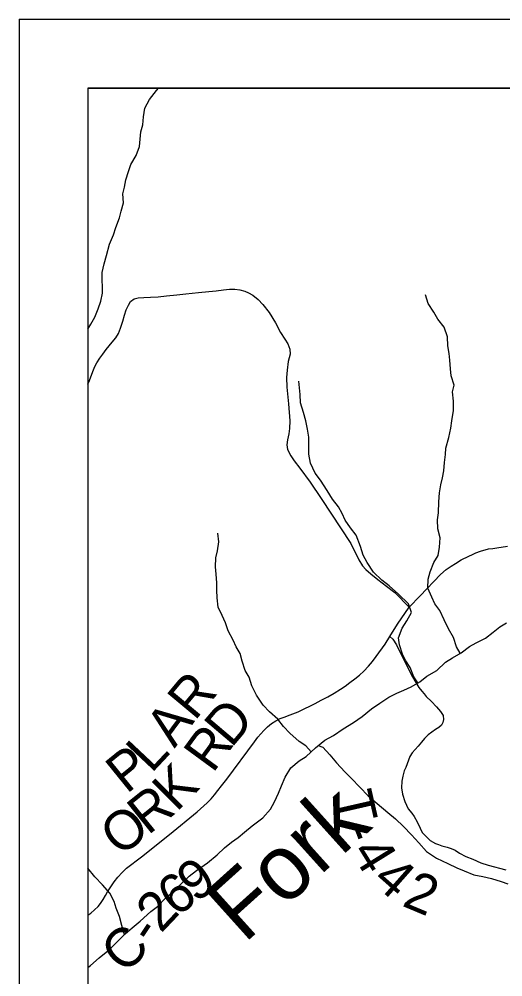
# Model space of a CAD drawing. Extents: x 0 to 82.7, y -0.2 to 22.
# Drawn here: x 2 to 2.703, y 19.61 to 21 of the extents above; entities that cross this region are included whole.
import ezdxf

# ---------------------------------------------------------------- set-up
doc = ezdxf.new("R2010")
doc.units = 0
for name, color, linetype in [('GM_X_County_Road', 7, 'Continuous'), ('GM_X_County_Road_Text', 7, 'Continuous'), ('GM_X_Minor_River', 7, 'Continuous'), ('GM_X_Minor_River_Text', 7, 'Continuous'), ('GM_X_Township_Road', 7, 'Continuous'), ('GM_X_Township_Road_Text', 7, 'Continuous'), ('GM_X_Township_Text', 7, 'Continuous'), ('SH_Cut_Line', 7, 'Continuous'), ('SH_Data', 7, 'Continuous')]:
    doc.layers.add(name, color=color, linetype=linetype)

msp = doc.modelspace()

# ---------------------------------------------------------------- linework, layer by layer
at = {"layer": 'GM_X_County_Road'}
msp.add_lwpolyline([(2.1, 19.6997), (2.104, 19.7025), (2.1093, 19.7073), (2.1147, 19.7124), (2.1182, 19.7168), (2.1218, 19.7224), (2.1256, 19.7283), (2.1283, 19.7333), (2.1382, 19.748), (2.1435, 19.755), (2.1495, 19.7616), (2.1558, 19.7678), (2.1777, 19.7842), (2.2186, 19.8167), (2.2584, 19.8497), (2.2732, 19.8629), (2.2789, 19.8684), (2.2836, 19.8742), (2.2885, 19.8805), (2.2937, 19.8872), (2.3016, 19.897), (2.3419, 19.9513), (2.3467, 19.9578), (2.3553, 19.9676), (2.3608, 19.9728), (2.3666, 19.9777), (2.3727, 19.9816), (2.3792, 19.985), (2.385, 19.9869), (2.3938, 19.9904), (2.4051, 19.9949), (2.4139, 19.9992), (2.4233, 20.0036), (2.43, 20.007), (2.4385, 20.0116), (2.4483, 20.0166), (2.4573, 20.0218), (2.4668, 20.0276), (2.4734, 20.0321), (2.4803, 20.0373), (2.4874, 20.0426), (2.4941, 20.0478), (2.5008, 20.0536), (2.5073, 20.0608), (2.5134, 20.0679), (2.5187, 20.0751), (2.5314, 20.0932), (2.5385, 20.1041), (2.5496, 20.1219), (2.5663, 20.1466), (2.5824, 20.163), (2.6121, 20.1939), (2.62, 20.2011), (2.6275, 20.2063), (2.6338, 20.21), (2.6421, 20.2153), (2.653, 20.2207), (2.6585, 20.2233), (2.6634, 20.2255), (2.6702, 20.2281), (2.6815, 20.2312), (2.6878, 20.232), (2.6939, 20.2329), (2.7091, 20.235)], dxfattribs=at)
at = {"layer": 'GM_X_Minor_River'}
for points in [[(2.1, 20.5502), (2.1043, 20.5572), (2.11, 20.5674), (2.115, 20.5795), (2.1185, 20.5905), (2.1209, 20.6022), (2.121, 20.6117), (2.1207, 20.6212), (2.1204, 20.6322), (2.1235, 20.6451), (2.127, 20.6572), (2.1313, 20.6735), (2.1371, 20.6871), (2.1402, 20.6977), (2.1456, 20.7117), (2.1483, 20.7215), (2.1515, 20.7332), (2.1508, 20.7465), (2.1528, 20.7564), (2.1548, 20.767), (2.159, 20.7787), (2.1621, 20.7893), (2.1698, 20.8021), (2.1748, 20.8154), (2.1757, 20.826), (2.1769, 20.8366), (2.1796, 20.8468), (2.1805, 20.8582), (2.1825, 20.8707), (2.1894, 20.8835), (2.1997, 20.8967), (2.2022, 20.9)], [(2.6406, 20.0797), (2.6354, 20.0892), (2.6306, 20.1025), (2.6235, 20.1151), (2.6172, 20.1281), (2.6109, 20.1418), (2.6037, 20.1513), (2.5996, 20.1612), (2.5937, 20.1741), (2.5938, 20.1874), (2.5969, 20.198), (2.6023, 20.2116), (2.6085, 20.2218), (2.6104, 20.2335), (2.6113, 20.2472), (2.608, 20.2601), (2.6074, 20.2734), (2.6089, 20.2836), (2.6094, 20.2995), (2.6103, 20.3128), (2.6123, 20.3242), (2.615, 20.3344), (2.6166, 20.3446), (2.6178, 20.3567), (2.6191, 20.3681), (2.6195, 20.3776), (2.6242, 20.3927), (2.6269, 20.4063), (2.6282, 20.4173), (2.6309, 20.4321), (2.631, 20.4454), (2.6296, 20.459), (2.632, 20.4689), (2.6272, 20.4826), (2.6265, 20.4925), (2.6255, 20.505), (2.6244, 20.5148), (2.6226, 20.5259), (2.6223, 20.5388), (2.6171, 20.5528), (2.6081, 20.5647), (2.6022, 20.5749), (2.5939, 20.5872), (2.5902, 20.5997)], [(2.579, 20.0367), (2.5734, 20.0457), (2.5678, 20.059), (2.5618, 20.0689), (2.557, 20.0785), (2.5522, 20.0918), (2.5511, 20.102), (2.5565, 20.116), (2.563, 20.127), (2.5699, 20.139), (2.5655, 20.1516), (2.5509, 20.1657), (2.5373, 20.1776), (2.5268, 20.186), (2.5148, 20.1975), (2.5054, 20.2116), (2.4994, 20.2219), (2.4958, 20.2348), (2.4895, 20.2512), (2.4812, 20.2619), (2.4733, 20.2729), (2.4693, 20.2824), (2.4637, 20.2923), (2.455, 20.3034), (2.4472, 20.316), (2.4375, 20.3308), (2.43, 20.3411), (2.4233, 20.3556), (2.4207, 20.3685), (2.4208, 20.3791), (2.4206, 20.3932), (2.4188, 20.405), (2.4166, 20.4171), (2.4129, 20.4293), (2.4085, 20.443), (2.4082, 20.4555), (2.4061, 20.4745)], [(2.424, 19.9366), (2.4166, 19.9453), (2.4065, 19.9515), (2.3929, 19.9637), (2.3839, 19.9733), (2.3757, 19.9839), (2.3637, 19.995), (2.3546, 20.0046), (2.3449, 20.0191), (2.3378, 20.0324), (2.3341, 20.0449), (2.3285, 20.0549), (2.3241, 20.0685), (2.3212, 20.0796), (2.3152, 20.0891), (2.3107, 20.0986), (2.3036, 20.1123), (2.2996, 20.1241), (2.2947, 20.1344), (2.2892, 20.1469), (2.2874, 20.1602), (2.2871, 20.1712), (2.2872, 20.1822), (2.2861, 20.1947), (2.2851, 20.205), (2.2855, 20.2183), (2.2879, 20.2285), (2.2899, 20.2414), (2.2885, 20.2539)], [(2.1312, 19.6499), (2.1426, 19.6608), (2.1541, 19.6725), (2.164, 19.6815), (2.1758, 19.6909), (2.1914, 19.7052), (2.2009, 19.7123), (2.2128, 19.7243), (2.2257, 19.7356), (2.236, 19.7454), (2.2471, 19.7563), (2.2577, 19.7645), (2.2737, 19.7758), (2.2874, 19.7871), (2.2981, 19.7976), (2.3084, 19.8055), (2.3179, 19.8122), (2.3275, 19.8201), (2.3385, 19.8295), (2.3541, 19.8408), (2.3652, 19.8536), (2.371, 19.8641), (2.3767, 19.8766), (2.381, 19.8876), (2.3864, 19.9001), (2.3948, 19.9133), (2.4066, 19.9238), (2.4169, 19.9298), (2.4302, 19.9426), (2.444, 19.9538), (2.4565, 19.9606), (2.4706, 19.9703), (2.4858, 19.9793), (2.4984, 19.9879), (2.5117, 19.9992), (2.5239, 20.0074), (2.5368, 20.016), (2.5486, 20.022), (2.5585, 20.0261), (2.5695, 20.031), (2.582, 20.0384), (2.5919, 20.0467), (2.6068, 20.0549), (2.6193, 20.0666), (2.6296, 20.073), (2.6418, 20.0805), (2.6543, 20.0895), (2.6639, 20.0951), (2.6775, 20.1018), (2.6886, 20.1104), (2.6981, 20.1179), (2.7076, 20.1239)], [(2.4341, 19.9458), (2.4412, 19.9436), (2.4514, 19.9325), (2.4611, 19.9207), (2.4731, 19.9077), (2.4825, 19.8978), (2.5069, 19.8729), (2.5201, 19.8615), (2.5355, 19.8488), (2.5468, 19.8396), (2.558, 19.8285), (2.5697, 19.8163), (2.5806, 19.8045), (2.5918, 19.7923), (2.6061, 19.7823), (2.6227, 19.7746), (2.6359, 19.7684), (2.6465, 19.7641), (2.6604, 19.758), (2.6733, 19.7556), (2.6861, 19.7528), (2.7001, 19.7486), (2.7099, 19.7451)], [(2.1529, 19.6713), (2.1492, 19.6846), (2.1456, 19.6976), (2.1407, 19.7097), (2.1378, 19.7196), (2.1318, 19.7318), (2.1209, 19.7436), (2.1097, 19.7555), (2.1, 19.7679)], [(2.1, 19.6239), (2.1034, 19.6266), (2.1163, 19.6379), (2.1312, 19.6499)]]:
    msp.add_lwpolyline(points, dxfattribs=at)
at = {"layer": 'GM_X_Township_Road'}
for points in [[(2.1, 20.4703), (2.1024, 20.4758), (2.1068, 20.4885), (2.1097, 20.4957), (2.1128, 20.5011), (2.117, 20.508), (2.1216, 20.5139), (2.1262, 20.5206), (2.1352, 20.531), (2.1405, 20.5377), (2.1442, 20.5438), (2.1472, 20.5516), (2.1505, 20.5618), (2.1528, 20.5706), (2.1555, 20.5782), (2.1587, 20.5849), (2.1616, 20.5901), (2.1671, 20.5939), (2.1727, 20.5955), (2.1811, 20.5962), (2.1907, 20.5966), (2.202, 20.5972), (2.2138, 20.5987), (2.2288, 20.6001), (2.242, 20.6014), (2.2607, 20.6035), (2.2757, 20.605), (2.286, 20.6058), (2.2967, 20.6073), (2.3055, 20.6081), (2.3134, 20.6081), (2.3205, 20.607), (2.3277, 20.6054), (2.3333, 20.6026), (2.3396, 20.5993), (2.3469, 20.593), (2.354, 20.5857), (2.363, 20.5742), (2.3723, 20.5593), (2.3798, 20.5453), (2.3861, 20.5354), (2.3901, 20.5287), (2.393, 20.5212), (2.3934, 20.5139), (2.3909, 20.503), (2.3892, 20.4908), (2.3882, 20.48), (2.3888, 20.4657), (2.3911, 20.4418), (2.3929, 20.4171), (2.3926, 20.4058), (2.3915, 20.3983), (2.3896, 20.3897), (2.3886, 20.382), (2.3898, 20.3755), (2.3944, 20.3663), (2.3995, 20.3589), (2.4078, 20.3483), (2.4229, 20.3282), (2.4388, 20.3045), (2.4816, 20.239), (2.4933, 20.2153), (2.4989, 20.2065), (2.5037, 20.2013), (2.5109, 20.1948), (2.5207, 20.187), (2.5333, 20.177), (2.5456, 20.168), (2.5663, 20.1466)], [(2.5385, 20.1041), (2.5427, 20.1003), (2.5481, 20.0918), (2.5699, 20.0482), (2.576, 20.0372), (2.5804, 20.0302), (2.585, 20.0248), (2.5881, 20.0208), (2.5913, 20.017), (2.5988, 20.0097), (2.6059, 20.0021), (2.6118, 19.9954), (2.6156, 19.9892), (2.6164, 19.9837), (2.6153, 19.9793), (2.6133, 19.9756), (2.6093, 19.9722), (2.6045, 19.9689), (2.5992, 19.9651), (2.5938, 19.9613), (2.5885, 19.9563), (2.5844, 19.9506), (2.5793, 19.9448), (2.5751, 19.9402), (2.571, 19.9354), (2.5674, 19.9297), (2.5636, 19.9194), (2.5617, 19.9138), (2.5594, 19.9092), (2.5571, 19.9012), (2.5557, 19.8941), (2.5553, 19.8845), (2.5569, 19.8751), (2.5603, 19.8646), (2.5651, 19.8541), (2.5703, 19.8476), (2.5739, 19.8428), (2.5783, 19.8351), (2.5823, 19.8259), (2.5852, 19.8196), (2.5906, 19.8141), (2.5971, 19.8078), (2.6049, 19.8039), (2.6091, 19.8022), (2.6139, 19.8005), (2.6214, 19.7984), (2.6275, 19.7965), (2.6331, 19.794), (2.6394, 19.7898), (2.6486, 19.785), (2.6587, 19.7808), (2.6704, 19.7754), (2.6811, 19.7723), (2.7069, 19.7655)]]:
    msp.add_lwpolyline(points, dxfattribs=at)
at = {"layer": 'GM_X_Township_Text'}
msp.add_lwpolyline([(6.1272, 20.9), (2.1, 20.9), (2.1, 19.5964), (2.2742, 19.1826), (2.3145, 19.0873), (2.397, 18.8926), (2.4438, 18.782), (2.7199, 18.1299), (2.7784, 18.9951), (2.7788, 19.0007), (2.8288, 19.7415), (2.8645, 20.2693), (2.8645, 20.2703), (2.8651, 20.279), (2.884, 20.5583), (3.179, 20.5374), (3.6288, 20.5056), (5.9672, 20.3493), (5.9756, 20.3782)], close=True, dxfattribs=at)
at = {"layer": 'SH_Cut_Line'}
msp.add_lwpolyline([(4.1209, 14.8338), (3.8036, 15.5496), (3.6125, 15.9807), (3.4071, 16.476), (3.2909, 16.7562), (3.0556, 17.2782), (3.0279, 17.3486), (2.7199, 18.1299), (2.7784, 18.9951), (2.7788, 19.0007), (2.8288, 19.7415), (2.8645, 20.2693), (2.8645, 20.2703), (2.8651, 20.279), (2.884, 20.5583), (3.179, 20.5374), (3.6288, 20.5056), (5.9672, 20.3493), (5.9756, 20.3782), (6.1272, 20.9), (2.1, 20.9), (2.1, 14.1)], dxfattribs=at)
at = {"layer": 'SH_Data'}
for p, q in [((2, 21), (9, 21)), ((2, 21), (2, 14)), ((2.1, 20.9), (2.1, 14.1)), ((2.1, 20.9), (8.9, 20.9))]:
    msp.add_line(p, q, dxfattribs=at)

# ---------------------------------------------------------------- texts
at = {"layer": 'GM_X_County_Road_Text'}
for s, rotation, p in [('R', 50.2149, (2.2549, 19.9805)), ('D', 49.7282, (2.3081, 19.9412)), ('A', 53.4542, (2.2257, 19.941)), ('R', 53.7697, (2.2812, 19.9044)), ('L', 46.7505, (2.1919, 19.9045)), ('P', 39.0149, (2.156, 19.8746)), ('K', 45.1103, (2.2285, 19.8485)), ('R', 38.7902, (2.187, 19.8147)), ('O', 37.4437, (2.1462, 19.7834)), ('9', 36.1517, (2.2562, 19.7168)), ('6', 36.2152, (2.2279, 19.6961)), ('2', 46.5567, (2.2059, 19.6725)), ('C', 44.8082, (2.1535, 19.6127)), ('-', 56.22, (2.1945, 19.6551))]:
    msp.add_text(s, height=0.0568, rotation=rotation, dxfattribs=at).set_placement(p)
at = {"layer": 'GM_X_Minor_River_Text'}
msp.add_text('Fork', height=0.09469, rotation=41.9992, dxfattribs=at).set_placement((2.3266, 19.6573))
at = {"layer": 'GM_X_Township_Road_Text'}
for s, rotation, p in [('T', 282.8663, (2.4555, 19.8733)), ('-', 290.757, (2.4675, 19.8237)), ('4', 301.8595, (2.481, 19.7911)), ('4', 318.581, (2.5111, 19.7477)), ('2', 337.3121, (2.5545, 19.7138))]:
    msp.add_text(s, height=0.0568, rotation=rotation, dxfattribs=at).set_placement(p)

doc.saveas('drawing.dxf')
